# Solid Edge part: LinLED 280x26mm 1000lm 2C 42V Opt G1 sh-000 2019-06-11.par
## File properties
Author: sylwester.cabaj
Template: iso metric part.par
Last saved by: sylwester.cabaj
Revision: 3
Application: Solid Edge
Gęstość: 0,000 kg/m^3
Dokładność: 0,990
Username: sylwester.cabaj
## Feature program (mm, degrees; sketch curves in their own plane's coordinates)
body "unnamed Body 1"
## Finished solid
Body 1: solid body, 955 faces, 2456 edges, 1564 vertices.
  Faces by surface: plane 656, cylinder 139, spline 96, cone 30, sphere 16, torus 10, spun 8
  Edges by curve: line 1822, curve on surface 324, circle 190, ellipse 66, spline 50, intersection 4
Bounding box of the edges (mm; curved faces can reach further): 279.000 x 5.050 x 26.000, from (-139.5, -3.45, -13) to (139.5, 1.6, 13).
Cylindrical faces by radius (mm): R0.2 x46, R0.2169 x6, R0.25 x12, R0.3373 x6, R0.4 x8, R0.4006 x2, R0.4008 x2, R0.525 x2, R0.6 x20, R1 x8, R1.1 x4, R1.2 x10, R2 x8, R2.15 x5
Conical faces (half-angle, radius in mm at the cone's reference point): 0.5 deg R0.5056 x4, 0.5 deg R1.0082 x4, 1 deg R0.5511 x2, 10 deg R0.2132 x4, 10 deg R0.4132 x4, 18.8604 deg R1.0669 x4, 27.363 deg R0.6214 x2, 45 deg R0.575 x2, 45 deg R0.625 x4
Toroidal faces (ring radius, tube radius in mm): R0.8 r0.2 x4, R0.8522 r0.3 x2, R0.9002 r0.2 x2, R0.9018 r0.2 x2
Spherical faces by radius (mm): R0.2 x12, R0.6 x4
Planar faces by outward normal: +x 76, +y 9, +z 77, -x 76, -y 109, -z 77, oblique 232
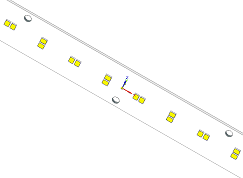
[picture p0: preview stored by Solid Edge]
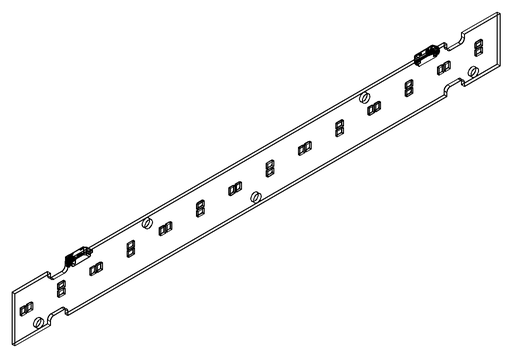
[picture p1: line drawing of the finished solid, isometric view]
